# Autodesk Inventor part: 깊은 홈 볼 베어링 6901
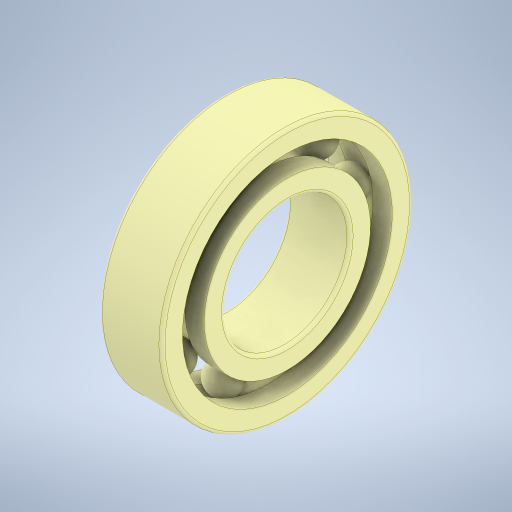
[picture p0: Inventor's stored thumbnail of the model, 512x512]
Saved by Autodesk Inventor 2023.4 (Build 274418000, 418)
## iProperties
Created: 2024-05
Part Number: 깊은 홈 볼 베어링 6901
Material: 강철, 연강
Description: 깊은 그루브 볼 베어링
Document SubType Name: Modeling
Designer: user
Density: 7.85 g/cm^3
Appearance: 기본값
Author: jhkim
Sending System: Autodesk Inventor 2025
Preprocessor: ST-DEVELOPER v20
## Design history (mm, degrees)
feature "Solid1"
feature "Solid1:1"
feature "Solid1:2"
feature "Solid1:3"
feature "Solid1:4"
feature "Solid1:5"
feature "Solid1:6"
feature "Solid1:7"
feature "Solid1:8"
feature "Solid1:9"
feature "Solid1:10"
node "솔리드1"
node "솔리드2"
node "솔리드3"
node "솔리드4"
node "솔리드5"
node "솔리드6"
node "솔리드7"
node "솔리드8"
node "솔리드9"
node "솔리드10"
node "솔리드11"
